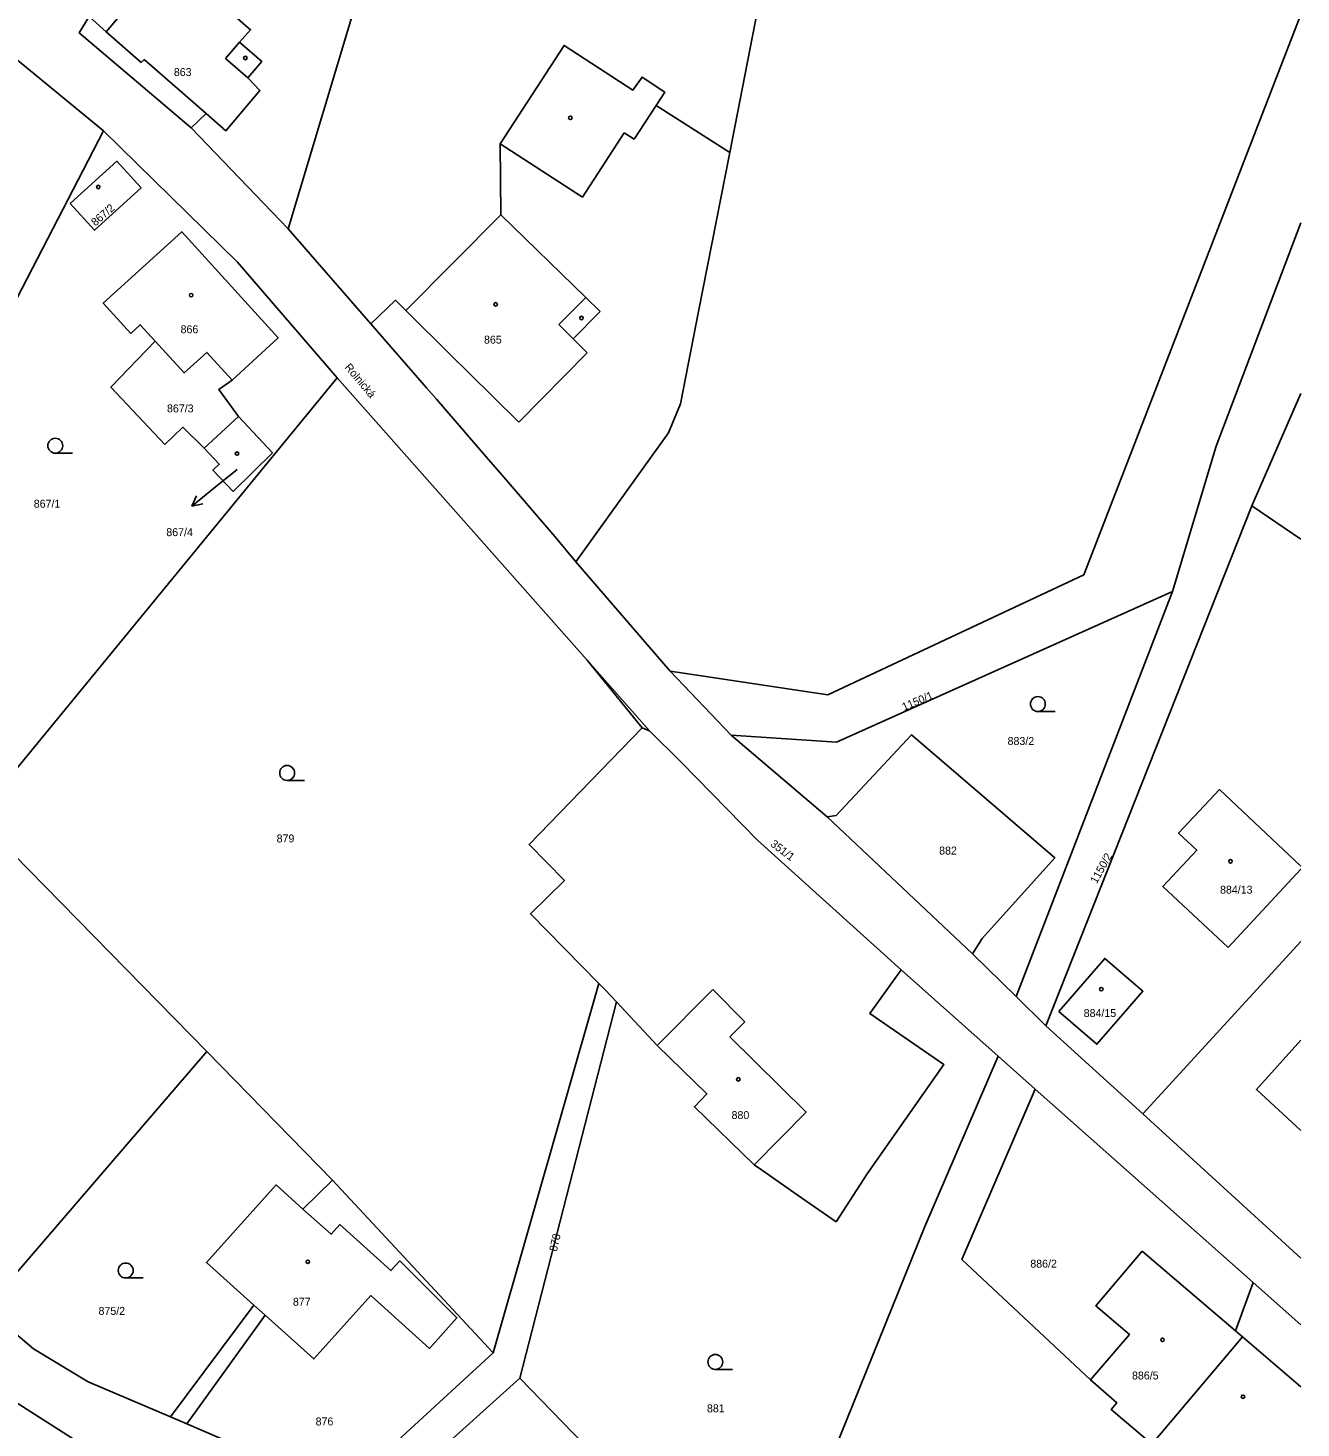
# Model space of a CAD drawing. Extents: x -719706 to -718922, y -950351 to -949651.
# Drawn here: x -719050.5 to -718922.2, y -949873.5 to -949732.4 of the extents above; entities that cross this region are included whole.
import ezdxf

# ---------------------------------------------------------------- set-up
doc = ezdxf.new("R2010")
doc.units = 0
doc.layers.add('Doplňující texty', color=7, linetype='Continuous')

msp = doc.modelspace()

# ---------------------------------------------------------------- linework, layer by layer
at = {"layer": 'Doplňující texty'}
for p, q in [((-719024.28, -949752.64), (-719010.42, -949706.36)), ((-718979.78, -949744.95), (-718974.43, -949717.63)), ((-719054.48, -949733.29), (-719042.89, -949742.78)), ((-719039.09, -949735.9), (-719042.64, -949732.79)), ((-719029.18, -949733.84), (-719030.61, -949735.47)), ((-719030.61, -949735.47), (-719028.37, -949737.43)), ((-719038.8, -949735.57), (-719039.09, -949735.9)), ((-719032.55, -949741.04), (-719038.8, -949735.57)), ((-718989.4, -949743.62), (-718987.2, -949740.23)), ((-719024.28, -949752.64), (-719034.08, -949742.47)), ((-719042.89, -949742.78), (-719066.99, -949789.29)), ((-718994.64, -949749.47), (-718990.41, -949742.96)), ((-718990.41, -949742.96), (-718989.4, -949743.62)), ((-719002.92, -949744.09), (-718994.64, -949749.47)), ((-719002.84, -949751.22), (-718994.29, -949759.55)), ((-719015.95, -949762.22), (-719024.28, -949752.64)), ((-719007.81, -949765.43), (-719012.44, -949760.86)), ((-718994.29, -949759.55), (-718997.01, -949762.3)), ((-718994.29, -949759.55), (-718992.85, -949760.97)), ((-718992.85, -949760.97), (-718995.57, -949763.72)), ((-718997.01, -949762.3), (-718995.57, -949763.72)), ((-718995.57, -949763.72), (-718994.14, -949765.13)), ((-719006.11, -949767.11), (-719007.81, -949765.43)), ((-718994.14, -949765.13), (-719001.04, -949772.11)), ((-719055.65, -949811.9), (-719019.34, -949767.65)), ((-719001.04, -949772.11), (-719006.11, -949767.11)), ((-719032.76, -949774.73), (-719029.3, -949771.54)), ((-719047.76, -949775.25), (-719046.01, -949775.25)), ((-719029.43, -949776.88), (-719031.66, -949778.69)), ((-719031.66, -949778.69), (-719033.99, -949780.58)), ((-719033.99, -949780.58), (-719033.53, -949779.56)), ((-719033.99, -949780.58), (-719032.9, -949780.34)), ((-718927.18, -949780.57), (-718947.91, -949832.94)), ((-718922.21, -949783.92), (-718927.18, -949780.57)), ((-718985.79, -949797.2), (-718995.28, -949786.21)), ((-718950.92, -949829.98), (-718935.17, -949789.18)), ((-718994.15, -949796.1), (-718988.61, -949802.91)), ((-718979.65, -949803.65), (-718985.79, -949797.2)), ((-718948.73, -949801.28), (-718946.98, -949801.28)), ((-718969.98, -949811.9), (-718979.65, -949803.65)), ((-719024.39, -949808.22), (-719022.64, -949808.22)), ((-719032.5, -949835.55), (-719055.65, -949811.9)), ((-718955.32, -949825.69), (-718969.98, -949811.9)), ((-718950.92, -949829.98), (-718955.32, -949825.69)), ((-718938.16, -949841.83), (-718922.21, -949824.45)), ((-718962.51, -949827.3), (-718952.74, -949836.01)), ((-718992.97, -949828.68), (-719003.64, -949865.91)), ((-718987.11, -949834.93), (-718981.48, -949829.3)), ((-718981.48, -949829.3), (-718978.25, -949832.55)), ((-718947.91, -949832.94), (-718950.92, -949829.98)), ((-719000.95, -949868.45), (-718991.21, -949830.52)), ((-718978.25, -949832.55), (-718979.78, -949834.07)), ((-718972.09, -949841.66), (-718979.78, -949834.07)), ((-718938.16, -949841.83), (-718947.91, -949832.94)), ((-719019.82, -949848.51), (-719032.5, -949835.55)), ((-718952.74, -949836.01), (-718949, -949839.33)), ((-718949, -949839.33), (-718927.02, -949858.82)), ((-718972.09, -949841.66), (-718977.31, -949846.94)), ((-718922.21, -949856.36), (-718938.16, -949841.83)), ((-719022.8, -949851.41), (-719019.82, -949848.51)), ((-719003.64, -949865.91), (-719019.82, -949848.51)), ((-719040.66, -949858.35), (-719038.91, -949858.35)), ((-718928.81, -949863.69), (-718927.02, -949858.82)), ((-718927.02, -949858.82), (-718922.21, -949863.08)), ((-719027.74, -949861.09), (-719026.61, -949862.1)), ((-718928.81, -949863.69), (-718928.11, -949864.29)), ((-719018.77, -949879.79), (-719003.64, -949865.91)), ((-718981.24, -949867.56), (-718979.49, -949867.56)), ((-719014.89, -949880.97), (-719000.95, -949868.45)), ((-719036.15, -949872.35), (-719034.51, -949873.05)), ((-719034.51, -949873.05), (-719018.77, -949879.79))]:
    msp.add_line(p, q, dxfattribs=at)
for points in [[(-719044.34, -949731.26), (-719042.64, -949732.79), (-719038.67, -949728.09), (-719036.59, -949729.91), (-719034.23, -949727.21), (-719028.08, -949732.59), (-719029.18, -949733.84), (-719026.94, -949735.79), (-719028.37, -949737.43), (-719027.13, -949738.7), (-719030.58, -949742.76), (-719032.55, -949741.04), (-719034.08, -949742.47)], [(-718922.21, -949731.05), (-718944.1, -949787.5), (-718969.91, -949799.6), (-718985.79, -949797.2)], [(-719034.08, -949742.47), (-719045.34, -949732.9), (-719044.34, -949731.26)], [(-719015.95, -949762.22), (-719013.47, -949759.84), (-719012.44, -949760.86), (-719002.84, -949751.22), (-719002.92, -949744.09), (-718996.48, -949734.17), (-718989.54, -949738.67), (-718988.62, -949737.35), (-718986.32, -949738.88), (-718987.2, -949740.23), (-718979.78, -949744.95)], [(-719042.89, -949742.78), (-719029.39, -949756), (-719019.34, -949767.65)], [(-718995.28, -949786.21), (-718985.97, -949773.2), (-718984.74, -949770.27), (-718982.92, -949760.97), (-718979.78, -949744.95)], [(-719046.26, -949750.09), (-719041.57, -949745.83), (-719039.11, -949748.53), (-719043.81, -949752.79), (-719046.26, -949750.09)], [(-718935.17, -949789.18), (-718930.75, -949774.53), (-718922.21, -949752.05)], [(-719029.93, -949767.9), (-719025.28, -949763.63), (-719035.02, -949752.94), (-719042.92, -949760.14), (-719040.15, -949763.18), (-719039.2, -949762.31), (-719037.68, -949763.98)], [(-718995.28, -949786.21), (-718997.41, -949783.65), (-719002.32, -949777.95), (-719004.32, -949775.61), (-719009.35, -949769.81), (-719010.34, -949768.67), (-719015.95, -949762.22)], [(-719032.76, -949774.73), (-719034.91, -949772.64), (-719036.72, -949774.37), (-719042.15, -949768.59), (-719037.68, -949763.98)], [(-719037.68, -949763.98), (-719034.77, -949767.17), (-719032.5, -949765.1), (-719029.93, -949767.9)], [(-719029.93, -949767.9), (-719031.29, -949768.84), (-719029.3, -949771.54)], [(-719019.34, -949767.65), (-718994.15, -949796.1), (-718987.86, -949803.21)], [(-718922.21, -949769.24), (-718927.18, -949780.57)], [(-719029.3, -949771.54), (-719025.88, -949775.2), (-719029.84, -949779.11), (-719031.87, -949776.97), (-719031.24, -949776.37), (-719032.76, -949774.73)], [(-718935.17, -949789.18), (-718969.01, -949804.38), (-718979.65, -949803.65)], [(-718992.97, -949828.68), (-718999.88, -949821.68), (-718996.44, -949818.29), (-719000.01, -949814.67), (-718988.61, -949802.91), (-718987.86, -949803.21)], [(-718987.86, -949803.21), (-718984.67, -949806.37), (-718976.99, -949814.24), (-718962.51, -949827.3)], [(-718955.32, -949825.69), (-718954.35, -949824.14), (-718947.03, -949816.01), (-718961.45, -949803.62), (-718969.05, -949811.74), (-718969.98, -949811.9)], [(-718929.54, -949825.05), (-718936.12, -949818.92), (-718932.71, -949815.24), (-718934.54, -949813.53), (-718930.44, -949809.15), (-718922.21, -949816.86)], [(-718922.21, -949817.18), (-718929.54, -949825.05)], [(-718946.6, -949831.52), (-718941.99, -949826.16), (-718938.15, -949829.47), (-718942.77, -949834.8), (-718946.6, -949831.52)], [(-718991.21, -949830.52), (-718987.11, -949834.93), (-718982.08, -949839.8), (-718983.34, -949841.1), (-718977.31, -949846.94), (-718976.48, -949847.54), (-718972.98, -949849.97), (-718969.07, -949852.68), (-718965.95, -949847.87), (-718958.21, -949836.84), (-718965.65, -949831.71), (-718962.51, -949827.3)], [(-718991.21, -949830.52), (-718992.31, -949829.35), (-718992.97, -949828.68)], [(-719052.4, -949863.41), (-719053.91, -949860.42), (-719032.5, -949835.55)], [(-718922.21, -949843.5), (-718926.71, -949839.35), (-718922.21, -949834.38)], [(-718976.47, -949893.65), (-718960.12, -949853.18), (-718952.74, -949836.01)], [(-718949, -949839.33), (-718956.38, -949856.5), (-718943.44, -949868.63)], [(-719036.15, -949872.35), (-719027.74, -949861.09), (-719032.53, -949856.78), (-719025.51, -949848.97), (-719022.8, -949851.41)], [(-719022.8, -949851.41), (-719019.97, -949853.95), (-719019.09, -949852.97), (-719013.93, -949857.61), (-719013.05, -949856.63), (-719007.28, -949862.37), (-719010.05, -949865.45), (-719015.97, -949860.13), (-719021.71, -949866.51), (-719026.61, -949862.1), (-719034.51, -949873.05)], [(-719033.87, -949882.27), (-719054.24, -949869.28), (-719063.9, -949853.6)], [(-718943.44, -949868.63), (-718939.49, -949864.06), (-718942.9, -949861.15), (-718938.21, -949855.66), (-718934.77, -949858.6), (-718928.81, -949863.69)], [(-719052.4, -949863.41), (-719049.95, -949865.5), (-719044.43, -949868.81), (-719036.15, -949872.35)], [(-718937.22, -949875.09), (-718936.66, -949874.42), (-718929.73, -949866.21), (-718928.11, -949864.29)], [(-718928.11, -949864.29), (-718922.21, -949869.33)], [(-719000.95, -949868.45), (-718995.57, -949873.98), (-718992.56, -949877.08), (-718984.13, -949885.77)], [(-718943.44, -949868.63), (-718940.78, -949870.93), (-718941.35, -949871.59), (-718937.82, -949874.58)]]:
    msp.add_lwpolyline(points, dxfattribs=at)
for centre, radius in [((-719028.6, -949735.43), 0.175), ((-718995.85, -949741.46), 0.175), ((-719043.43, -949748.43), 0.175), ((-719034.06, -949759.33), 0.175), ((-719003.38, -949760.26), 0.175), ((-718994.73, -949761.63), 0.175), ((-719047.76, -949774.5), 0.75), ((-719029.44, -949775.29), 0.175), ((-718948.73, -949800.53), 0.75), ((-719024.39, -949807.47), 0.75), ((-718929.31, -949816.37), 0.175), ((-718942.34, -949829.25), 0.175), ((-718978.92, -949838.34), 0.175), ((-719022.3, -949856.72), 0.175), ((-719040.66, -949857.6), 0.75), ((-718936.16, -949864.58), 0.175), ((-718981.24, -949866.81), 0.75), ((-718928.06, -949870.32), 0.175)]:
    msp.add_circle(centre, radius, dxfattribs=at)

# ---------------------------------------------------------------- texts
for s, p in [('863', (-719035.81, -949737.25)), ('866', (-719035.13, -949763.17)), ('865', (-719004.55, -949764.21)), ('867/3', (-719036.5, -949771.14)), ('867/1', (-719049.93, -949780.74)), ('867/4', (-719036.57, -949783.61)), ('883/2', (-718951.78, -949804.65)), ('879', (-719025.45, -949814.47)), ('882', (-718958.68, -949815.69)), ('884/13', (-718930.37, -949819.63)), ('884/15', (-718944.11, -949832.06)), ('880', (-718979.6, -949842.34)), ('886/2', (-718949.49, -949857.31)), ('877', (-719023.81, -949861.15)), ('875/2', (-719043.4, -949862.07)), ('886/5', (-718939.24, -949868.58)), ('881', (-718982.08, -949871.89)), ('876', (-719021.52, -949873.21))]:
    msp.add_text(s, height=0.8, dxfattribs=at).set_placement(p)
for s, rotation, p in [('867/2', 41, (-719043.72, -949752.42)), ('Rolnická', 310, (-719018.64, -949766.62)), ('1150/1', 23, (-718962.22, -949801.23)), ('351/1', 323, (-718975.76, -949814.77)), ('1150/2', 61, (-718942.8, -949818.69)), ('878', 77, (-718997.22, -949855.74))]:
    msp.add_text(s, height=0.8, rotation=rotation, dxfattribs=at).set_placement(p)

doc.saveas('drawing.dxf')
